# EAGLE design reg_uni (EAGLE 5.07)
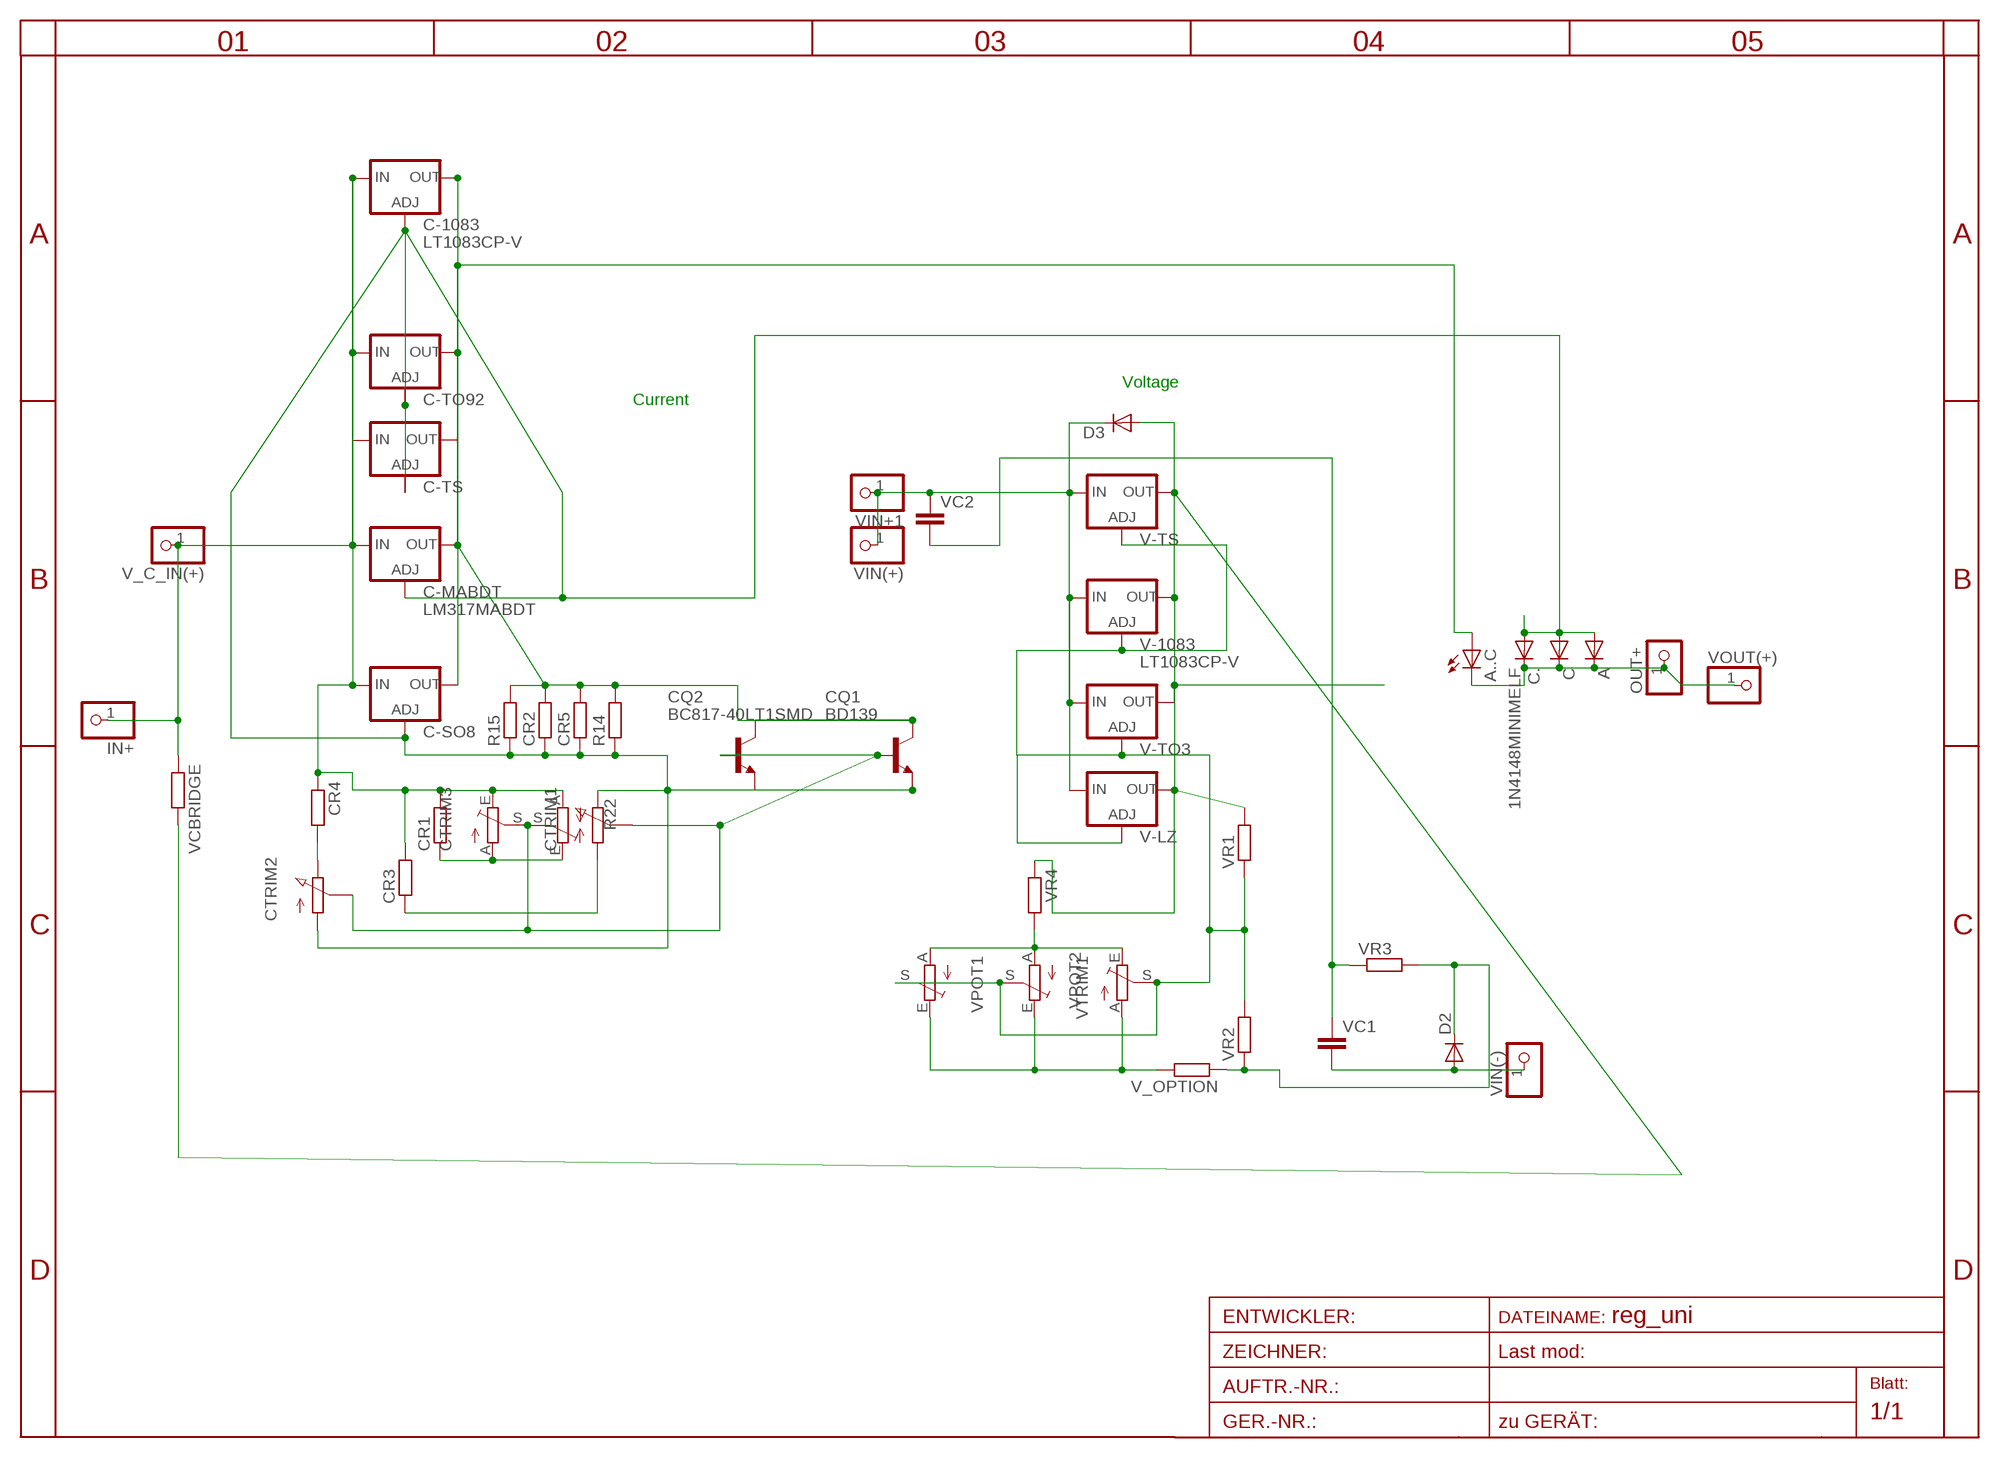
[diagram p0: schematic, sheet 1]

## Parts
A  DIODE-TO220V  [TO220ACS]
A..C  LED3MM  [LED3MM]
C  DIODE-SMB  [SMB]
C-1083  LT1083CP-V  [TO247S]
C-MABDT  LM317MABDT  [DPACK]
C-SO8  LM317LM-OUTPIN7  [SO08]
C-TO92  LM317LZ  [317L]
C-TS  LM317TS  [317TS]
C.  1N4148MINIMELF  [MINIMELF]
CQ1  BD139  [TO126V]
CQ2  BC817-40LT1SMD  [SOT23-BEC]
CR1  R-EU_0207/15  [0207/15]
CR2  R-EU_R1206  [R1206]
CR3  R-EU_R1206  [R1206]
CR4  R-EU_R1206  [R1206]
CR5  R-EU_R1206  [R1206]
CTRIM1  PC25  [PC25]
CTRIM2  PC25  [PC25]
CTRIM3  TRIM_EU-S64W  [S64W]
D2  DIODE-MINIMELF  [MINIMELF]
D3  DIODE-MINIMELF  [MINIMELF]
IN+  PINHD-1X1  [1X01]
OUT+  PINHD-1X1  [1X01]
R14  R-EU_R1206  [R1206]
R15  R-EU_R1206  [R1206]
R22  TRIM_EU-RAND160  [RANDL]
V-1083  LT1083CP-V  [TO247S]
V-LZ  LM317LZ  [317L]
V-TO3  LM317-TO3  [TO3-K02]
V-TS  LM317TS  [317TS]
V_C_IN(+)  PINHD-1X11MM6  [1X1MM8]
V_OPTION  R-EU_R0402  [R0402]
VC1  C-EU050-025X075  [C050-025X075]
VC2  C-EU050-025X075  [C050-025X075]
VCBRIDGE  R-EU_R0402  [R0402]
VIN(+)  PINHD-1X11MM6  [1X1MM8]
VIN(-)  PINHD-1X1  [1X01]
VIN+1  PINHD-1X1  [1X01]
VOUT(+)  PINHD-1X11MM6  [1X1MM8]
VPOT1  TRIM_EU-RAND160  [RANDL]
VPOT2  TRIM_EU-S64W  [S64W]
VR1  R-EU_0204/5  [0204/5]
VR2  R-EU_0204/7  [0204/7]
VR3  R-EU_0207/12  [0207/12]
VR4  R-EU_0207/12  [0207/12]
VTRIM1  TRIM_EU-EVND_H  [EVND8AA]

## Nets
ADJ2: V-1083.1(ADJ) V-LZ.1(ADJ) V-TO3.2(ADJ) V-TS.1(ADJ) VPOT1.S VPOT2.S VR1.1 VR2.2 VTRIM1.S
ADJUST: A.A C-1083.1(ADJ) C-MABDT.1(ADJ) C-SO8.4(ADJ) C-TO92.1(ADJ) C-TS.1(ADJ) C..A C.A CQ1.3(E) CQ2.E CR2.1 CR5.1 CTRIM1.E CTRIM2.A R14.1 R15.1
B1: CQ1.1(B) CQ2.B CTRIM1.S CTRIM2.S CTRIM3.S R22.S
IN+1: D3.C V-1083.3(IN) V-LZ.3(IN) V-TO3.1(IN) V-TS.3(IN) VC2.1 VIN(+).1 VIN+1.1
IN-: D2.A VC1.2 VIN(-).1
INPUT+: C-1083.3(IN) C-MABDT.3(IN) C-SO8.1(IN) C-TO92.3(IN) C-TS.3(IN) CR1.2 CR3.2 CR4.1 CTRIM3.E IN+.1 R22.A V_C_IN(+).1 VCBRIDGE.1
MINUS: CR1.1 CTRIM3.A R22.E
N$1: V_OPTION.2 VPOT1.E VPOT2.A VTRIM1.E
N$2: VPOT1.A VPOT2.E VR4.2 VTRIM1.A
N$5: CR3.1 CTRIM1.A
N$6: CR4.2 CTRIM2.E
N$7: VC1.1 VC2.2 VR3.1
OUT1: A..C.A C-1083.2(OUT) C-MABDT.4(OUT) C-SO8.7(OUT) C-TO92.2(OUT) C-TS.2(OUT) CQ1.2(C) CQ2.C CR2.2 CR5.2 R14.2 R15.2
OUT2: D3.A V-1083.2(OUT) V-LZ.2(OUT) V-TO3.3(OUT) V-TS.2(OUT) VCBRIDGE.2 VR1.2 VR4.1
OUT+: A..C.K(C) A.C C..C C.C OUT+.1 VOUT(+).1
VIRT-: D2.C V_OPTION.1 VR2.1 VR3.2

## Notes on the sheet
- Voltage
- Current

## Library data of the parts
A C D2 D3 = diode:DIODE-: DIODE
A..C = led:LED: LED
C-1083 V-1083 = linear-technology-2:LT1083*: 7.5A Low Dropout Positive Adjustable Regulators
C-MABDT = v-reg:LM317?*: 500 mA Adjustable Output Positive Voltage Regulator Source: http://www.onsemi.co.jp .. LM317M-D.PDF
C-SO8 C-TO92 V-LZ = v-reg-3:LM317L: Adjustable Voltage Regulator, 1.2V to 37V, 100mA
C-TS V-TS = v-reg:LM317TS: VOLTAGE REGULATOR
C. = diode-1:1N4148: DIODE
CQ1 = transistor-npn:BD139*: NPN Transistor
CQ2 = transistor-npn:BC817*: NPN Transistor
CR1-CR5 R14 R15 V_OPTION VCBRIDGE VR1-VR4 = rcl-2:R-EU_: RESISTOR, European symbol
CTRIM1 CTRIM2 = pot-vitrohm:PC25: VITROHM POTENTIOMETER
CTRIM3 R22 VPOT1 VPOT2 VTRIM1 = pot:TRIM_EU-: POTENTIOMETER
IN+ OUT+ VIN(-) VIN+1 = pinhead(2):PINHD-1X1: PIN HEADER
V-TO3 = v-reg:LM317-TO3: VOLTAGE REGULATOR
V_C_IN(+) VIN(+) VOUT(+) = pinhead:PINHD-1X1: PIN HEADER
VC1 VC2 = rcl:C-EU: CAPACITOR, European symbol

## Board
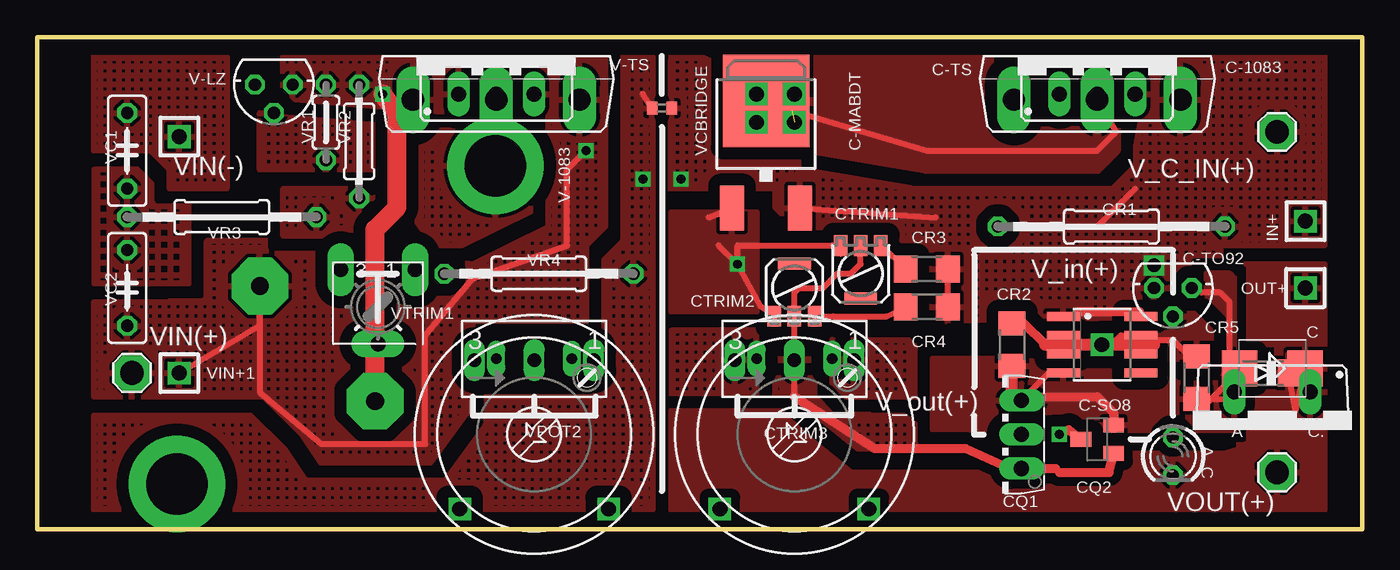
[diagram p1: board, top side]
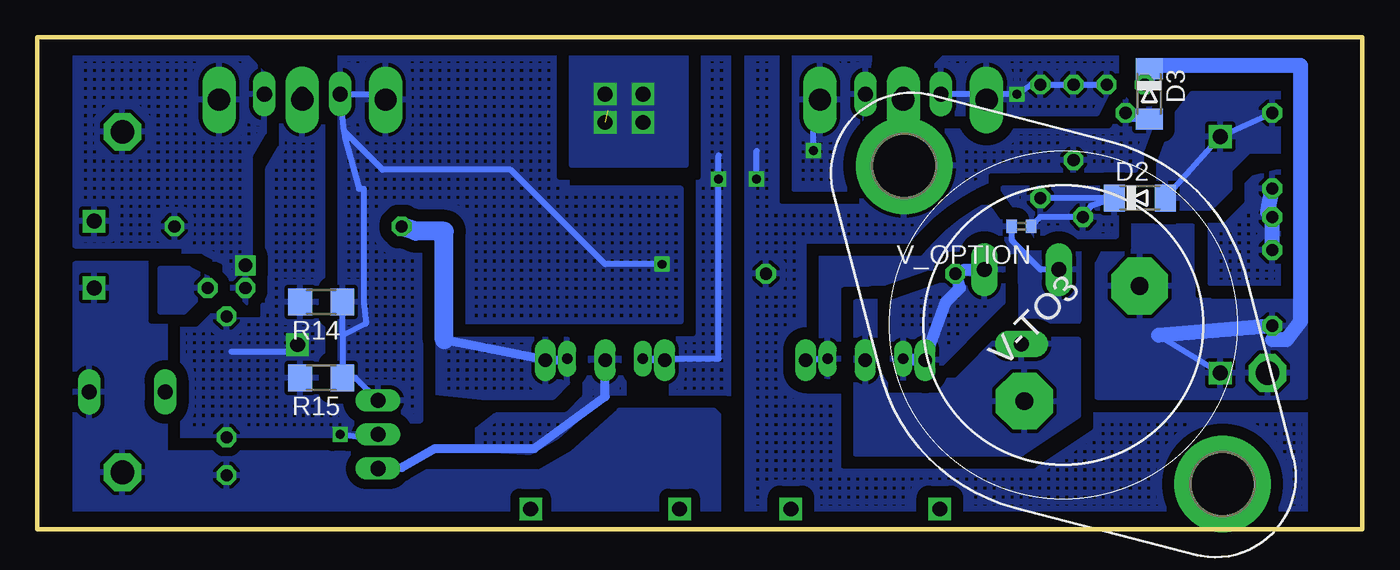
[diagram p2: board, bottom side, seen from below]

Size 88.9 x 33.02 mm. Coordinates in mm from the lower left corner, seen from the top.
Outline: 0,0 88.9,0 88.9,33.02 0,33.02 0,0
Copper layers (1*16): Top 0.035mm / dielectric 1.5mm / Bottom 0.035mm
Design rules "default": minimum track width 10mil, minimum drill 24mil, track to track 8mil, track to pad 8mil, pad to pad 8mil, via to via 8mil, smd to smd 8mil, copper to edge 40mil, drill to drill 8mil, minimum pad ring 10mil, minimum via ring 8mil, stop-mask expansion 4mil, vias tented up to drill 0mil, thermal gap 10mil

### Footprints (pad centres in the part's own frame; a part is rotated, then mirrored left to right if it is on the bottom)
TO220ACS = drill 1.016 long: A 2.54,-2.54; C -2.54,-2.54
LED3MM = drill 0.813 octagon: A -1.27,0; K 1.27,0
SMB = smd 2.4 x 2.4: A 2.2,0; C -2.2,0
TO247S = drill 1.499 long: 1 -5.588,-2.921; 2 0,-2.921; 3 5.588,-2.921
DPACK = smd 1.6 x 3: 1 -2.28,-4.8; 3 2.28,-4.8 | smd 5.8 x 6.2: 4 0,2.38
SO08 = smd 0.6 x 2.2: 1 -1.905,-2.6; 2 -0.635,-2.6; 3 0.635,-2.6; 4 1.905,-2.6; 5 1.905,2.6; 6 0.635,2.6; 7 -0.635,2.6; 8 -1.905,2.6
317L = drill 0.813 octagon: 1 -1.27,0; 2 0,1.905; 3 1.27,0
317TS = drill 1.016 long: 1 -2.54,-2.54; 2 0,-2.54; 3 2.54,-2.54
MINIMELF = smd 1.4 x 1.8: A 1.7,0; C -1.7,0
TO126V = drill 1.016 long: 1 -2.286,-1.27; 2 0,-1.27; 3 2.286,-1.27
SOT23-BEC = smd 1 x 1.4: B -0.95,-1.1; C 0,1.1; E 0.95,-1.1
0207/15 = drill 0.813 octagon: 1 -7.62,0; 2 7.62,0
R1206 = smd 1.6 x 1.803: 1 -1.422,0; 2 1.422,0
PC25 = smd 2.2 x 0.8: 4 0,1.65 | smd 0.9 x 1.4: A -1.35,-1.9; E 1.35,-1.9; S 0,-1.9
S64W = drill 0.7 long: A 2.54,1.27; E -2.54,1.27; S 0,1.27
1X01 = drill 1.016 square: 1 0,0
RANDL = drill 0.9 long: A -4,5; E 4,5; S 0,5 | drill 1 square: P$1 -5,-5; P$2 5,-5
TO3-K02 = drill 1.194 pad 3.81 octagon: 1 -1.778,-5.461; 2 -1.778,5.461 | drill 4.115 pad 6.477 round: 3 15.113,0; 3@ -15.113,0
1X1MM8 = drill 1.6 pad 2.54 octagon: 1 0,0
R0402 = smd 0.7 x 0.9: 1 -0.65,0; 2 0.65,0
C050-025X075 = drill 0.813 octagon: 1 -2.54,0; 2 2.54,0
0204/5 = drill 0.813 octagon: 1 -2.54,0; 2 2.54,0
0204/7 = drill 0.813 octagon: 1 -3.81,0; 2 3.81,0
0207/12 = drill 0.813 octagon: 1 -6.35,0; 2 6.35,0
EVND8AA = drill 1 pad 1.778 long: A -2.5,-2.5; E 2.5,-2.5; S 0,2.5

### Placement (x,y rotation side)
A  82.87,6.67 180 top
A..C  76.2,4.89 270 top
C  82.87,10.79 180 top
C-1083  71.12,31.75 0 top
C-MABDT  48.9,26.35 0 top
C-SO8  71.44,12.38 270 top
C-TO92  76.2,16.19 180 top
C-TS  71.12,31.75 0 top
C.  82.23,10.48 180 top
CQ1  64.77,6.35 90 top
CQ2  71.12,6.03 90 top
CR1  72.07,20.32 0 top
CR2  65.41,12.38 90 top
CR3  59.69,17.46 0 top
CR4  59.69,14.92 180 top
CR5  77.79,10.16 90 top
CTRIM1  55.24,17.14 180 top
CTRIM2  50.8,16.19 0 top
CTRIM3  50.8,10.16 0 top
D2  14.92,22.23 0 bottom
D3  14.29,29.21 270 bottom
IN+  85.09,20.67 0 top
OUT+  85.09,16.19 90 top
R14  69.85,15.24 180 bottom
R15  69.85,10.16 180 bottom
R22  50.8,6.35 0 top
V-1083  30.8,31.75 0 top
V-LZ  15.88,29.84 180 top
V-TO3  20.06,13.71 135 bottom
V-TS  30.8,31.75 0 top
V_C_IN(+)  83.19,26.67 0 top
V_OPTION  22.86,20.32 180 bottom
VC1  6.03,25.4 90 top
VC2  6.03,16.19 90 top
VCBRIDGE  41.91,28.26 180 top
VIN(+)  6.35,10.48 0 top
VIN(-)  9.53,26.35 0 top
VIN+1  9.53,10.48 0 top
VOUT(+)  83.19,3.81 0 top
VPOT1  33.34,6.35 0 top
VPOT2  33.34,10.16 0 top
VR1  19.37,27.3 270 top
VR2  21.59,26.04 90 top
VR3  12.38,20.95 0 top
VR4  33.66,17.14 180 top
VTRIM1  22.86,14.92 180 top

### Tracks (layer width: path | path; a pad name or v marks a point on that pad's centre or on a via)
ADJ2  (via drill 0.6)
  Top 1.27: V-TO3.2 22.66,20.12 24.13,21.59 24.13,27.94 v23.18,29.21
  Bottom 0.406: V-LZ.1 VR1.1 VR2.2 22.23,29.84 v23.18,29.21 24.13,29.21 24.86,28.48 | 24.86,28.48 V-1083.1 25.59,29.21 V-TS.1 | 24.86,28.48 24.32,27.94
  pour Bottom (isolate 0.813, hatched): 16.51,30.48 16.51,31.75 27.94,31.75 29.21,30.48 29.21,29.21 27.94,27.94 17.78,27.94
  pour Bottom (isolate 0.813, rank 3): 19.05,12.7 24.77,12.7 25.72,11.75 32.38,10.16 32.38,15.24 33.97,15.24 33.97,5.08 22.86,5.08 19.05,7.62
  pour Top (isolate 0.813, hatched): 16.51,31.75 27.94,31.75 29.21,30.48 29.21,29.21 27.94,27.94 16.51,28.89
ADJUST  (via drill 0.6)
  Top 0.406: C-SO8.4 67.88,10.48 CQ1.3 | CQ1.3 65.98,8.57 | CQ1.3 65.41,9.27 | 45.05,20.92 C-MABDT.1 | CTRIM2.A 48.57,14.93 v46.99,17.78 | CTRIM1.E 53.9,18.5 53.34,19.05 46.99,19.05 v46.99,17.78 | v46.99,17.78 45.72,19.05 | 72.22,7.62 72.22,7.15 | C..A 78.27,8.26 CR5.1 79.86,8.74 80.01,8.89 80.01,15.24 79.38,15.88 78.11,15.88 C-TO92.1 | A.A C.A
  Top 0.61: CQ2.E 72.22,7.62 72.22,7.79 71.12,8.89 66.29,8.89 CQ1.3
  Top 0.813: 65.41,9.27 CR2.1
  Bottom 0.406: R15.1 68.58,10.01 | 68.3,26.7 68.26,26.35 67.31,22.86 66.99,22.86 66.99,15.24 66.84,13.8 68.43,13.02 | 68.3,26.7 C-TS.1 65.91,29.21 C-1083.1 | 68.43,13.02 R15.1 | 68.43,13.02 R14.1 | v46.99,17.78 50.8,17.78 57.15,24.13 65.73,24.13 68.3,26.7 | R15.1 67.56,10.16 CQ1.3
  pour Top (isolate 0.813): 42.55,21.27 48.26,21.27 48.26,14.61 42.55,14.61
  pour Top (isolate 0.813, rank 2): 60.07,11.43 60.07,6.67 80.33,6.67 80.33,16.83 80.01,17.14 78.42,17.14 78.42,9.84 74.93,10.16 72.39,10.16 71.12,11.43
  pour Bottom (isolate 0.61): 77.47,16.19 77.47,16.83 78.74,17.46 80.64,17.46 80.64,14.61 79.06,14.61
  pour Bottom (isolate 0.813, rank 3, hatched): 53.34,31.75 68.58,31.75 68.58,10.16 64.77,7.3 63.18,7.3 63.18,20.32 60.96,20.32 60.96,13.97 45.72,13.97 45.72,22.86 53.34,22.86
B1
  Top 0.406: 68.33,4.06 68.58,3.81 | CTRIM3.S CTRIM2.S 50.8,15.88 51.12,16.19 52.7,16.19 53.66,17.14 54.61,17.14 55.24,17.78 CTRIM1.S | 50.8,8.89 R22.S | CQ1.1 65.79,3.81
  Top 0.61: CQ2.B 71.9,3.81 68.58,3.81 | CQ1.1 68.33,4.06 | 65.79,3.81 62.29,5.4 56.2,5.4 50.8,8.89
  Bottom 0.406: 64.45,4.13 CQ1.1
  Bottom 0.61: 64.45,4.13 62.23,5.4 55.56,5.4 50.8,8.89 CTRIM3.S
  pour Bottom (isolate 0.813, rank 6, hatched): 49.53,11.43 52.07,11.43 55.88,7.62 58.1,7.62 59.37,6.67 59.37,5.4 54.61,5.08 52.39,6.67 50.8,6.99 49.53,8.26
  pour Top (isolate 0.813, rank 6, hatched): 49.53,11.43 52.07,11.43 55.88,7.62 58.1,7.62 59.37,6.67 59.37,5.4 53.66,5.4 50.8,6.99 49.53,8.26
IN+1  (via drill 0.6)
  Top 0.406: v36.83,25.4 35.56,24.13 35.56,19.05 29.21,16.83 26.04,13.02 26.04,5.71 19.05,5.71 14.94,9.19 V-TO3.1 14.94,13.67 VIN+1.1
  Bottom 0.406: 13.65,13.02 VIN+1.1 | 6.03,12.7 VC2.1 | v36.83,25.4 36.83,28.38 V-1083.3 | D3.C 14.22,30.91 14.22,30.61
  Bottom 1.016: VC2.1 13.65,13.02 | V-LZ.3 14.22,30.61 13.97,31.11 4.13,31.11 4.13,13.97 5.08,12.7 6.03,12.7
  pour Bottom (isolate 0.813, hatched): 33.02,31.75 38.1,31.75 38.1,22.86 34.29,22.86
  pour Top (isolate 0.813, rank 3, hatched): 3.81,15.24 8.89,15.24 11.43,19.37 17.78,19.37 29.21,17.78 34.29,20.32 34.29,30.48 33.02,31.75 38.1,31.75 38.1,20.32 36.83,19.05 36.83,13.97 29.21,13.97 28.89,7.94 26.35,4.45 19.05,4.45 17.78,6.35 15.24,8.89 3.81,8.89
  pour Bottom (isolate 0.813, rank 3): 17.78,17.78 17.78,8.89 3.81,8.89 3.81,15.24 10.16,15.24 11.43,16.51 11.43,20.32 16.51,20.32
IN-
  Bottom 0.406: VC1.2 VIN(-).1 D2.A
  pour Bottom (isolate 0.813): 5.08,29.21 11.43,29.21 12.38,27.94 13.65,24.45 13.65,21.59 10.16,21.59 8.89,22.86 8.89,24.13 7.62,25.4 5.08,25.4
  pour Top (isolate 0.813, hatched): 3.81,31.75 12.7,31.75 12.7,22.86 8.89,22.86 8.89,24.13 7.62,25.4 3.81,25.4
INPUT+  (via drill 0.6, 0.9)
  Top 0.406: CR4.1 CR3.2 | C-SO8.1 69.53,14.29 69.85,14.61 | C-MABDT.3 60.29,20.92 | 69.85,20.32 71.12,20.32 73.66,22.86
  Top 0.61: 69.85,14.61 73.98,14.61
  Bottom 0.406: R22.A 48.26,11.35 CTRIM3.E 43.18,11.43 v43.18,23.5 43.18,25.08
  other vias: 74.93,17.7
  pour Top (isolate 0.813, rank 5, hatched): 74.93,31.75 86.36,31.75 86.36,19.05 79.38,19.05 79.38,14.29 60.96,13.97 57.15,13.97 49.53,21.59 49.53,22.86 41.91,22.86 42.55,31.75 44.45,31.75 62.23,24.13 73.66,24.13 73.66,25.4
  pour Bottom (isolate 0.813, rank 2, hatched): 75.25,31.75 86.36,32.07 86.36,19.05 79.06,19.05 79.06,17.78 77.47,14.92 74.61,15.24 74.61,25.08 73.66,26.67 73.66,30.48 74.93,31.75
  pour Bottom (isolate 0.813, rank 5, hatched): 42.55,31.75 42.55,8.89 46.35,8.89 45.09,31.75
  pour Top (isolate 0.813, rank 5, hatched): 42.55,13.34 42.55,8.89 48.26,8.89 48.26,13.34
MINUS
  Bottom 0.406: 53.42,11.35 CTRIM3.A
  Bottom 0.61: 61.59,12.7 R22.E 53.42,11.35
  Bottom 1.27: CR1.1 63.5,20 61.59,20 61.59,12.7
  pour Bottom (isolate 0.813, rank 4, hatched): 53.34,12.7 62.23,12.7 62.23,9.21 59.05,8.89 54.29,8.89 53.34,9.84
  pour Top (isolate 0.813, rank 4, hatched): 53.34,12.7 58.42,12.7 59.05,12.06 59.05,8.89 54.29,8.89 53.34,9.84
N$1
  Bottom 0.406: VTRIM1.E 21.59,17.42 23.5,19.37 V_OPTION.2 | VPOT2.A 37.34,11.43 VPOT1.E
  pour Bottom (isolate 0.813, rank 5): 37.78,10.48 37.15,18.1 35.56,19.05 29.21,19.05 26.67,21.59 21.59,21.59 19.05,19.05 19.05,13.97 22.86,13.97 22.86,16.51 24.13,17.78 26.67,17.78 27.94,16.51 33.02,16.51 35.05,15.24 35.05,10.16
N$2
  Bottom 0.813: VTRIM1.A 26.71,17.42 VR4.2 26.99,16.19 27.94,15.24 29.21,11.75 VPOT1.A 30.72,11.35 VPOT2.E
  pour Bottom (isolate 0.813, rank 2, hatched): 24.13,17.78 24.13,15.24 29.21,10.16 31.5,10.16 31.5,15.24
N$5
  Top 0.406: CTRIM1.A 57.64,18.09 CR3.1
N$6
  Top 0.406: 57.78,14.92 CR4.2 57,14.29 53.41,14.29 CTRIM2.E
N$7
  Bottom 0.406: VR3.1 6.35,21.27
  Bottom 1.016: VC2.2 VR3.1 | 6.35,21.27 VC1.1
  pour Bottom (isolate 0.813, rank 2, hatched): 5.08,24.13 5.08,16.51 10.16,16.51 10.16,22.86
  pour Top (isolate 0.813, rank 2, hatched): 3.81,24.13 3.81,16.51 10.16,16.51 10.16,24.13
OUT1  (via drill 0.6, 1)  (1 unrouted)
  Top 0.406: C-MABDT.4 50.64,28.1 59.69,25.4 71.12,25.4 72.39,26.67 C-1083.2 | v71.44,12.38 72.39,12.7 72.71,13.02 C-SO8.7 | CR2.2 66.21,13.8 | CR5.2 77.64,11.26 76.2,12.7 74.61,12.7 74.3,12.38
  Top 0.61: CQ2.C 69.22,6.67 v68.58,6.35 | 66.21,13.8 67.63,12.38
  Top 0.813: 74.93,12.38 74.3,12.38 v71.44,12.38 67.63,12.38
  Bottom 0.406: 66.36,6.03 v68.58,6.35 | 75.88,11.9 71.92,11.9 v71.44,12.38
  other vias: 48.26,29.21 50.8,29.21 50.8,27.3 48.26,27.3
  pour Bottom (isolate 0.813, rank 5, hatched): 69.85,28.89 73.34,29.53 74.3,22.23 74.3,14.29 78.11,14.29 79.38,13.65 79.69,6.03 66.67,6.03
  pour Top (isolate 0.813, rank 3): 52.07,31.75 73.66,31.75 72.39,29.21 72.39,25.4 71.12,24.13 59.69,24.13 52.07,25.4
  pour Bottom (isolate 0.813, rank 2): 45.4,31.75 45.4,24.45 53.02,24.45 53.02,31.75
  pour Top (isolate 0.813): 75.56,14.61 77.47,14.61 78.74,13.34 78.74,11.43 74.93,11.43
OUT2  (via drill 0.6)
  Top 0.406: VCBRIDGE.2 40.64,29.21
  Bottom 0.406: v40.64,23.5 40.64,25.4 | V-TO3.3 30.74,28.77 V-1083.2 V-TS.2 | D3.A 15.88,27.51 V-LZ.2
  pour Bottom (isolate 0.813, rank 4, hatched): 15.88,28.89 18.1,27.94 31.75,27.94 34.29,25.4 34.29,24.13 35.56,22.86 38.1,22.86 38.1,31.75 41.27,31.75 41.27,0.32 3.81,0 3.81,8.89 17.78,8.89 22.23,5.08 34.29,5.08 34.29,8.89 37.47,8.89 37.47,19.37 30.48,19.37 arc38 22.86,24.13 15.24,24.13 12.7,27.94
  pour Top (isolate 0.813, rank 4, hatched): 14.92,27.94 31.75,27.94 34.29,25.4 34.29,24.13 35.56,22.86 38.1,22.86 38.1,31.75 41.27,31.75 41.27,1.27 3.81,1.27 3.81,7.62 16.51,7.62 17.14,4.45 26.67,4.45 29.21,8.89 37.47,8.89 37.47,19.05 37.78,20.32 36.83,20.32 35.56,19.05 26.67,19.05 22.86,24.13 14.92,24.13
OUT+
  Top 0.406: C..C 84.43,7.94 C.C
  pour Top (isolate 0.61, rank 3): 80.96,17.78 86.36,17.78 86.36,1.27 85.72,0.64 43.18,0.64 42.55,1.27 42.55,7.94 49.85,7.94 51.44,6.35 54.61,3.81 71.12,3.81 71.12,5.08 79.69,5.08 80.64,5.4 80.64,9.21 83.19,9.21 83.19,12.38 80.96,12.38 80.96,13.34 80.64,13.65 80.64,17.46
  pour Bottom (isolate 0.61, rank 2): 80.33,17.78 86.36,17.78 86.36,1.27 85.72,0.64 43.18,0.64 43.18,7.62 43.5,7.94 49.85,7.94 53.02,5.08 55.24,3.81 64.14,3.81 64.14,4.76 65.09,5.08 80.33,5.08
VIRT-
  Bottom 0.406: V_OPTION.1 21.61,20.95 VR3.2 18.21,21.7 D2.C VR2.1
  pour Bottom (isolate 0.813, hatched): 16.51,22.86 24.13,22.86 21.91,19.68 16.51,19.68
  pour Top (isolate 0.813, hatched): 16.51,22.86 22.86,22.86 22.86,19.68 16.51,19.68

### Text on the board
tNames: V_in(+) | V_out(+)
